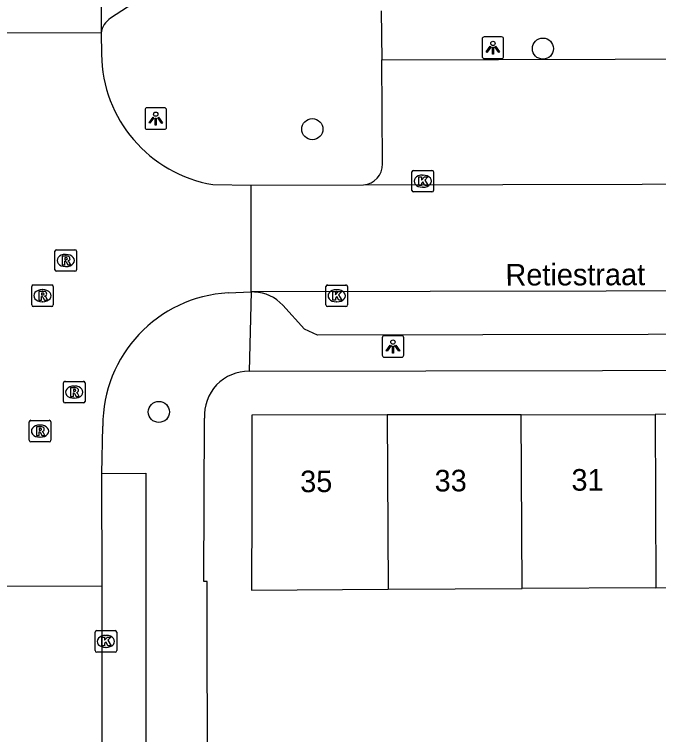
# Model space of a CAD drawing. Extents: x 160732 to 162105, y 387428 to 388479.
# Drawn here: x 161157.55 to 161187.37, y 387935.67 to 387969.02 of the extents above; entities that cross this region are included whole.
import ezdxf

# ---------------------------------------------------------------- set-up
doc = ezdxf.new("R2010")
doc.units = 0
for name, color, linetype in [('IMGEO_Boom', 7, 'Continuous'), ('IMGEO_Kolk', 7, 'Continuous'), ('IMGEO_Lichtpunt', 7, 'Continuous'), ('IMGEO_Openbare_ruimte_label', 7, 'Continuous'), ('IMGEO_Pand', 7, 'Continuous'), ('IMGEO_Pand_nummerreeks', 7, 'Continuous'), ('IMGEO_Rijbaan_lokaal_open', 7, 'Continuous'), ('IMGEO_Rioolput', 7, 'Continuous'), ('IMGEO_Voetpad_open', 7, 'Continuous')]:
    doc.layers.add(name, color=color, linetype=linetype)

msp = doc.modelspace()

# ---------------------------------------------------------------- linework, layer by layer
at = {"layer": 'IMGEO_Boom'}
for centre in [(161182.014, 387967.438), (161171.341, 387963.708), (161164.237, 387950.611)]:
    msp.add_circle(centre, 0.489, dxfattribs=at)
at = {"layer": 'IMGEO_Kolk'}
for p, q in [((161175.953, 387960.872), (161175.953, 387961.724)), ((161176.028, 387961.798), (161176.88, 387961.798)), ((161176.441, 387961.578), (161176.466, 387961.578)), ((161176.954, 387961.724), (161176.954, 387960.872)), ((161176.464, 387961.018), (161176.439, 387961.018)), ((161176.88, 387960.798), (161176.028, 387960.798)), ((161171.967, 387955.563), (161171.967, 387956.415)), ((161172.042, 387956.489), (161172.894, 387956.489)), ((161172.455, 387956.269), (161172.48, 387956.269)), ((161172.968, 387956.415), (161172.968, 387955.563)), ((161172.478, 387955.709), (161172.453, 387955.709)), ((161172.894, 387955.489), (161172.042, 387955.489)), ((161161.283, 387939.557), (161161.283, 387940.409)), ((161161.358, 387940.483), (161162.21, 387940.483)), ((161161.771, 387940.263), (161161.796, 387940.263)), ((161162.284, 387940.409), (161162.284, 387939.557)), ((161161.794, 387939.703), (161161.769, 387939.703)), ((161162.21, 387939.483), (161161.358, 387939.483))]:
    msp.add_line(p, q, dxfattribs=at)
for points in [[(161175.953, 387960.872), (161175.953, 387961.724)], [(161176.028, 387961.798), (161176.88, 387961.798)], [(161176.954, 387961.724), (161176.954, 387960.872)], [(161176.274, 387961.498), (161176.397, 387961.498), (161176.397, 387961.347), (161176.527, 387961.498), (161176.691, 387961.498), (161176.545, 387961.347), (161176.698, 387961.098), (161176.546, 387961.098), (161176.461, 387961.262), (161176.397, 387961.195), (161176.397, 387961.098), (161176.274, 387961.098), (161176.274, 387961.498)], [(161176.88, 387960.798), (161176.028, 387960.798)], [(161171.967, 387955.563), (161171.967, 387956.415)], [(161172.042, 387956.489), (161172.894, 387956.489)], [(161172.288, 387956.189), (161172.411, 387956.189), (161172.411, 387956.038), (161172.541, 387956.189), (161172.705, 387956.189), (161172.559, 387956.038), (161172.712, 387955.789), (161172.56, 387955.789), (161172.475, 387955.953), (161172.411, 387955.886), (161172.411, 387955.789), (161172.288, 387955.789), (161172.288, 387956.189)], [(161172.968, 387956.415), (161172.968, 387955.563)], [(161172.894, 387955.489), (161172.042, 387955.489)], [(161161.283, 387939.557), (161161.283, 387940.409)], [(161161.358, 387940.483), (161162.21, 387940.483)], [(161161.604, 387940.183), (161161.727, 387940.183), (161161.727, 387940.032), (161161.857, 387940.183), (161162.021, 387940.183), (161161.875, 387940.032), (161162.028, 387939.783), (161161.876, 387939.783), (161161.791, 387939.947), (161161.727, 387939.88), (161161.727, 387939.783), (161161.604, 387939.783), (161161.604, 387940.183)], [(161162.284, 387940.409), (161162.284, 387939.557)], [(161162.21, 387939.483), (161161.358, 387939.483)]]:
    msp.add_lwpolyline(points, dxfattribs=at)
for centre, start, end in [((161176.03, 387961.722), 91.552, 178.448), ((161176.03, 387961.722), 91.552, 178.448), ((161176.878, 387961.722), 1.552, 88.448), ((161176.878, 387961.722), 1.552, 88.448), ((161176.03, 387960.874), 181.552, 268.448), ((161176.03, 387960.874), 181.552, 268.448), ((161176.878, 387960.874), 271.552, 358.448), ((161176.878, 387960.874), 271.552, 358.448), ((161172.044, 387956.413), 91.552, 178.448), ((161172.044, 387956.413), 91.552, 178.448), ((161172.892, 387956.413), 1.552, 88.448), ((161172.892, 387956.413), 1.552, 88.448), ((161172.044, 387955.565), 181.552, 268.448), ((161172.044, 387955.565), 181.552, 268.448), ((161172.892, 387955.565), 271.552, 358.448), ((161172.892, 387955.565), 271.552, 358.448), ((161161.36, 387940.407), 91.552, 178.448), ((161161.36, 387940.407), 91.552, 178.448), ((161162.208, 387940.407), 1.552, 88.448), ((161162.208, 387940.407), 1.552, 88.448), ((161161.36, 387939.559), 181.552, 268.448), ((161161.36, 387939.559), 181.552, 268.448), ((161162.208, 387939.559), 271.552, 358.448), ((161162.208, 387939.559), 271.552, 358.448)]:
    msp.add_arc(centre, 0.0765, start, end, dxfattribs=at)
for centre, major_axis, ratio, start_param, end_param in [((161176.44, 387961.298), (-0.387, 0.002), 0.722429, 4.712389, 7.853982), ((161176.465, 387961.298), (-0.39, 0.002), 0.717154, 1.570796, 4.712389), ((161172.454, 387955.989), (-0.387, 0.002), 0.722429, 4.712389, 7.853982), ((161172.479, 387955.989), (-0.39, 0.002), 0.717154, 1.570796, 4.712389), ((161161.77, 387939.983), (-0.387, 0.002), 0.722429, 4.712389, 7.853982), ((161161.795, 387939.983), (-0.39, 0.002), 0.717154, 1.570796, 4.712389)]:
    msp.add_ellipse(centre, major_axis=major_axis, ratio=ratio, start_param=start_param, end_param=end_param, dxfattribs=at)
at = {"layer": 'IMGEO_Lichtpunt'}
for p, q in [((161179.201, 387967.881), (161179.201, 387967.074)), ((161179.201, 387967.881), (161179.201, 387967.074)), ((161180.103, 387967.976), (161179.295, 387967.976)), ((161180.103, 387967.976), (161179.295, 387967.976)), ((161180.197, 387967.074), (161180.197, 387967.881)), ((161180.197, 387967.074), (161180.197, 387967.881)), ((161179.295, 387966.98), (161180.103, 387966.98)), ((161179.295, 387966.98), (161180.103, 387966.98)), ((161163.596, 387964.603), (161163.596, 387963.796)), ((161163.596, 387964.603), (161163.596, 387963.796)), ((161164.498, 387964.698), (161163.69, 387964.698)), ((161164.498, 387964.698), (161163.69, 387964.698)), ((161164.592, 387963.796), (161164.592, 387964.603)), ((161164.592, 387963.796), (161164.592, 387964.603)), ((161163.69, 387963.702), (161164.498, 387963.702)), ((161163.69, 387963.702), (161164.498, 387963.702)), ((161174.575, 387954.045), (161174.575, 387953.238)), ((161174.575, 387954.045), (161174.575, 387953.238)), ((161175.477, 387954.14), (161174.669, 387954.14)), ((161175.477, 387954.14), (161174.669, 387954.14)), ((161175.571, 387953.238), (161175.571, 387954.045)), ((161175.571, 387953.238), (161175.571, 387954.045)), ((161174.669, 387953.144), (161175.477, 387953.144)), ((161174.669, 387953.144), (161175.477, 387953.144))]:
    msp.add_line(p, q, dxfattribs=at)
for points in [[(161179.575, 387967.545), (161179.614, 387967.517), (161179.426, 387967.255), (161179.388, 387967.282), (161179.575, 387967.545)], [(161179.787, 387967.517), (161179.825, 387967.544), (161180.012, 387967.282), (161179.973, 387967.254), (161179.787, 387967.517)], [(161179.677, 387967.497), (161179.724, 387967.497), (161179.724, 387967.175), (161179.677, 387967.175), (161179.677, 387967.497)], [(161163.97, 387964.267), (161164.009, 387964.239), (161163.821, 387963.977), (161163.783, 387964.004), (161163.97, 387964.267)], [(161164.072, 387964.219), (161164.119, 387964.219), (161164.119, 387963.897), (161164.072, 387963.897), (161164.072, 387964.219)], [(161164.182, 387964.239), (161164.22, 387964.266), (161164.407, 387964.004), (161164.368, 387963.976), (161164.182, 387964.239)], [(161174.949, 387953.709), (161174.988, 387953.681), (161174.8, 387953.419), (161174.762, 387953.446), (161174.949, 387953.709)], [(161175.051, 387953.661), (161175.098, 387953.661), (161175.098, 387953.339), (161175.051, 387953.339), (161175.051, 387953.661)], [(161175.161, 387953.681), (161175.199, 387953.708), (161175.386, 387953.446), (161175.347, 387953.418), (161175.161, 387953.681)]]:
    msp.add_lwpolyline(points, dxfattribs=at)
for centre in [(161179.7, 387967.679), (161164.095, 387964.401), (161175.074, 387953.843)]:
    msp.add_circle(centre, 0.0994, dxfattribs=at)
for centre, start, end in [((161179.295, 387967.881), 90, 180), ((161179.295, 387967.881), 90, 180), ((161180.103, 387967.881), 0, 90), ((161180.103, 387967.881), 0, 90), ((161179.295, 387967.074), 180, 270), ((161179.295, 387967.074), 180, 270), ((161180.103, 387967.074), 270, 0), ((161180.103, 387967.074), 270, 360), ((161163.69, 387964.603), 90, 180), ((161163.69, 387964.603), 90, 180), ((161164.498, 387964.603), 0, 90), ((161164.498, 387964.603), 0, 90), ((161163.69, 387963.796), 180, 270), ((161163.69, 387963.796), 180, 270), ((161164.498, 387963.796), 270, 0), ((161164.498, 387963.796), 270, 360), ((161174.669, 387954.045), 90, 180), ((161174.669, 387954.045), 90, 180), ((161175.477, 387954.045), 0, 90), ((161175.477, 387954.045), 0, 90), ((161174.669, 387953.238), 180, 270), ((161174.669, 387953.238), 180, 270), ((161175.477, 387953.238), 270, 0), ((161175.477, 387953.238), 270, 360)]:
    msp.add_arc(centre, 0.0946, start, end, dxfattribs=at)
at = {"layer": 'IMGEO_Pand'}
for points in [[(161174.808, 387950.47), (161168.535, 387950.459), (161168.535, 387946.227), (161168.521, 387942.361), (161174.849, 387942.396)], [(161181.005, 387950.481), (161174.808, 387950.47)], [(161174.808, 387950.47), (161174.849, 387942.396)], [(161181.005, 387950.481), (161187.204, 387950.491)], [(161181.048, 387942.431), (161181.005, 387950.481)], [(161193.403, 387950.502), (161187.204, 387950.491)], [(161187.204, 387950.491), (161187.247, 387942.466)], [(161187.247, 387942.466), (161193.447, 387942.501)], [(161174.849, 387942.396), (161181.048, 387942.431)], [(161187.247, 387942.466), (161181.048, 387942.431)]]:
    msp.add_lwpolyline(points, dxfattribs=at)
at = {"layer": 'IMGEO_Rijbaan_lokaal_open'}
for points in [[(161161.475, 388044.985), (161161.565, 387968.157)], [(161161.565, 387968.157), (161156.629, 387968.165)], [(161161.565, 387968.157), (161161.581, 387967.173)], [(161173.705, 387961.122), (161212.393, 387961.222), (161212.367, 387967.026)], [(161166.739, 387961.141), (161168.507, 387961.118)], [(161168.507, 387961.118), (161173.705, 387961.122)], [(161168.516, 387956.165), (161168.507, 387961.118)], [(161217.48, 387956.261), (161168.663, 387956.165)], [(161167.441, 387956.125), (161168.516, 387956.165)], [(161168.663, 387956.165), (161168.516, 387956.165)], [(161161.599, 387947.756), (161161.64, 387949.955)], [(161161.618, 387942.56), (161161.599, 387947.756)], [(161156.704, 387942.547), (161161.618, 387942.56)], [(161161.627, 387913.997), (161161.618, 387942.56)]]:
    msp.add_lwpolyline(points, dxfattribs=at)
for centre, radius, start, end in [((161167.769, 387967.243), 6.189, 180.6508, 260.4171), ((161167.792, 387949.983), 6.152, 93.2734, 180.2577)]:
    msp.add_arc(centre, radius, start, end, dxfattribs=at)
at = {"layer": 'IMGEO_Rioolput'}
for p, q in [((161159.427, 387957.198), (161159.427, 387958.05)), ((161159.502, 387958.124), (161160.354, 387958.124)), ((161159.915, 387957.904), (161159.94, 387957.904)), ((161160.428, 387958.05), (161160.428, 387957.198)), ((161159.938, 387957.344), (161159.913, 387957.344)), ((161160.354, 387957.124), (161159.502, 387957.124)), ((161158.349, 387955.568), (161158.349, 387956.42)), ((161158.424, 387956.494), (161159.276, 387956.494)), ((161158.837, 387956.274), (161158.862, 387956.274)), ((161159.35, 387956.42), (161159.35, 387955.568)), ((161158.86, 387955.714), (161158.835, 387955.714)), ((161159.276, 387955.494), (161158.424, 387955.494)), ((161159.817, 387951.101), (161159.817, 387951.953)), ((161159.892, 387952.027), (161160.744, 387952.027)), ((161160.818, 387951.953), (161160.818, 387951.101)), ((161160.305, 387951.807), (161160.33, 387951.807)), ((161160.328, 387951.247), (161160.303, 387951.247)), ((161160.744, 387951.027), (161159.892, 387951.027)), ((161158.31, 387950.221), (161159.162, 387950.221)), ((161158.235, 387949.295), (161158.235, 387950.147)), ((161158.723, 387950.001), (161158.748, 387950.001)), ((161159.236, 387950.147), (161159.236, 387949.295)), ((161159.162, 387949.221), (161158.31, 387949.221)), ((161158.746, 387949.441), (161158.721, 387949.441))]:
    msp.add_line(p, q, dxfattribs=at)
for points in [[(161159.427, 387957.198), (161159.427, 387958.05)], [(161159.502, 387958.124), (161160.354, 387958.124)], [(161160.428, 387958.05), (161160.428, 387957.198)], [(161160.016, 387957.822), (161159.764, 387957.824), (161159.764, 387957.424)], [(161159.764, 387957.424), (161159.888, 387957.424), (161159.888, 387957.586), (161159.899, 387957.586)], [(161159.942, 387957.743), (161159.888, 387957.743), (161159.888, 387957.662)], [(161159.888, 387957.662), (161159.94, 387957.662)], [(161159.946, 387957.557), (161160.017, 387957.424), (161160.157, 387957.424), (161160.092, 387957.55)], [(161160.354, 387957.124), (161159.502, 387957.124)], [(161158.349, 387955.568), (161158.349, 387956.42)], [(161158.424, 387956.494), (161159.276, 387956.494)], [(161158.938, 387956.192), (161158.686, 387956.194), (161158.686, 387955.794)], [(161159.35, 387956.42), (161159.35, 387955.568)], [(161158.686, 387955.794), (161158.81, 387955.794), (161158.81, 387955.956), (161158.821, 387955.956)], [(161158.864, 387956.113), (161158.81, 387956.113), (161158.81, 387956.032)], [(161158.81, 387956.032), (161158.862, 387956.032)], [(161158.868, 387955.927), (161158.939, 387955.794), (161159.079, 387955.794), (161159.014, 387955.92)], [(161159.276, 387955.494), (161158.424, 387955.494)], [(161159.817, 387951.101), (161159.817, 387951.953)], [(161159.892, 387952.027), (161160.744, 387952.027)], [(161160.818, 387951.953), (161160.818, 387951.101)], [(161160.406, 387951.725), (161160.154, 387951.727), (161160.154, 387951.327)], [(161160.332, 387951.646), (161160.278, 387951.646), (161160.278, 387951.565)], [(161160.278, 387951.565), (161160.33, 387951.565)], [(161160.154, 387951.327), (161160.278, 387951.327), (161160.278, 387951.489), (161160.289, 387951.489)], [(161160.336, 387951.46), (161160.407, 387951.327), (161160.547, 387951.327), (161160.482, 387951.453)], [(161160.744, 387951.027), (161159.892, 387951.027)], [(161158.31, 387950.221), (161159.162, 387950.221)], [(161158.235, 387949.295), (161158.235, 387950.147)], [(161158.824, 387949.919), (161158.572, 387949.921), (161158.572, 387949.521)], [(161158.75, 387949.84), (161158.696, 387949.84), (161158.696, 387949.759)], [(161159.236, 387950.147), (161159.236, 387949.295)], [(161158.572, 387949.521), (161158.696, 387949.521), (161158.696, 387949.683), (161158.707, 387949.683)], [(161158.696, 387949.759), (161158.748, 387949.759)], [(161158.754, 387949.654), (161158.825, 387949.521), (161158.965, 387949.521), (161158.9, 387949.647)], [(161159.162, 387949.221), (161158.31, 387949.221)]]:
    msp.add_lwpolyline(points, dxfattribs=at)
for centre, radius, start, end in [((161159.504, 387958.048), 0.0765, 91.552, 178.448), ((161159.504, 387958.048), 0.0765, 91.552, 178.448), ((161160.352, 387958.048), 0.0765, 1.552, 88.448), ((161160.352, 387958.048), 0.0765, 1.552, 88.448), ((161159.898, 387957.533), 0.0533, 26.0293, 88.6989), ((161159.924, 387957.851), 0.19, 274.7715, 282.9687), ((161159.948, 387957.647), 0.0964, 77.0061, 93.1865), ((161159.962, 387957.704), 0.0378, 276.6634, 79.6772), ((161160.015, 387957.712), 0.109, 350.3612, 89.416), ((161160.013, 387957.712), 0.112, 277.5842, 350.9817), ((161159.997, 387957.497), 0.108, 29.5134, 73.7905), ((161159.504, 387957.2), 0.0765, 181.552, 268.448), ((161159.504, 387957.2), 0.0765, 181.552, 268.448), ((161160.352, 387957.2), 0.0765, 271.552, 358.448), ((161160.352, 387957.2), 0.0765, 271.552, 358.448), ((161158.426, 387956.418), 0.0765, 91.552, 178.448), ((161158.426, 387956.418), 0.0765, 91.552, 178.448), ((161158.937, 387956.082), 0.109, 350.3612, 89.416), ((161159.274, 387956.418), 0.0765, 1.552, 88.448), ((161159.274, 387956.418), 0.0765, 1.552, 88.448), ((161158.82, 387955.903), 0.0533, 26.0293, 88.6989), ((161158.846, 387956.221), 0.19, 274.7715, 282.9687), ((161158.87, 387956.017), 0.0964, 77.0061, 93.1865), ((161158.884, 387956.074), 0.0378, 276.6634, 79.6772), ((161158.935, 387956.082), 0.112, 277.5842, 350.9817), ((161158.919, 387955.867), 0.108, 29.5134, 73.7905), ((161158.426, 387955.57), 0.0765, 181.552, 268.448), ((161158.426, 387955.57), 0.0765, 181.552, 268.448), ((161159.274, 387955.57), 0.0765, 271.552, 358.448), ((161159.274, 387955.57), 0.0765, 271.552, 358.448), ((161159.894, 387951.951), 0.0765, 91.552, 178.448), ((161159.894, 387951.951), 0.0765, 91.552, 178.448), ((161160.742, 387951.951), 0.0765, 1.552, 88.448), ((161160.742, 387951.951), 0.0765, 1.552, 88.448), ((161160.314, 387951.754), 0.19, 274.7715, 282.9687), ((161160.338, 387951.55), 0.0964, 77.0061, 93.1865), ((161160.352, 387951.607), 0.0378, 276.6634, 79.6772), ((161160.405, 387951.615), 0.109, 350.3612, 89.416), ((161160.403, 387951.615), 0.112, 277.5842, 350.9817), ((161160.288, 387951.436), 0.0533, 26.0293, 88.6989), ((161160.387, 387951.4), 0.108, 29.5134, 73.7905), ((161159.894, 387951.103), 0.0765, 181.552, 268.448), ((161159.894, 387951.103), 0.0765, 181.552, 268.448), ((161160.742, 387951.103), 0.0765, 271.552, 358.448), ((161160.742, 387951.103), 0.0765, 271.552, 358.448), ((161158.312, 387950.145), 0.0765, 91.552, 178.448), ((161158.312, 387950.145), 0.0765, 91.552, 178.448), ((161159.16, 387950.145), 0.0765, 1.552, 88.448), ((161159.16, 387950.145), 0.0765, 1.552, 88.448), ((161158.756, 387949.744), 0.0964, 77.0061, 93.1865), ((161158.77, 387949.801), 0.0378, 276.6634, 79.6772), ((161158.823, 387949.809), 0.109, 350.3612, 89.416), ((161158.706, 387949.63), 0.0533, 26.0293, 88.6989), ((161158.732, 387949.948), 0.19, 274.7715, 282.9687), ((161158.821, 387949.809), 0.112, 277.5842, 350.9817), ((161158.805, 387949.594), 0.108, 29.5134, 73.7905), ((161158.312, 387949.297), 0.0765, 181.552, 268.448), ((161158.312, 387949.297), 0.0765, 181.552, 268.448), ((161159.16, 387949.297), 0.0765, 271.552, 358.448), ((161159.16, 387949.297), 0.0765, 271.552, 358.448)]:
    msp.add_arc(centre, radius, start, end, dxfattribs=at)
for centre, major_axis, ratio, start_param, end_param in [((161159.914, 387957.624), (-0.387, 0.002), 0.722429, 4.712389, 7.853982), ((161159.939, 387957.624), (-0.39, 0.002), 0.717154, 1.570796, 4.712389), ((161158.836, 387955.994), (-0.387, 0.002), 0.722429, 4.712389, 7.853982), ((161158.861, 387955.994), (-0.39, 0.002), 0.717154, 1.570796, 4.712389), ((161160.304, 387951.527), (-0.387, 0.002), 0.722429, 4.712389, 7.853982), ((161160.329, 387951.527), (-0.39, 0.002), 0.717154, 1.570796, 4.712389), ((161158.722, 387949.721), (-0.387, 0.002), 0.722429, 4.712389, 7.853982), ((161158.747, 387949.721), (-0.39, 0.002), 0.717154, 1.570796, 4.712389)]:
    msp.add_ellipse(centre, major_axis=major_axis, ratio=ratio, start_param=start_param, end_param=end_param, dxfattribs=at)
at = {"layer": 'IMGEO_Voetpad_open'}
for points in [[(161163.479, 388022.652), (161163.652, 387970.452), (161163.55, 387970.033), (161163.307, 387969.717), (161162.002, 387968.854)], [(161174.53, 387969.19), (161174.563, 387966.923)], [(161174.563, 387966.923), (161212.367, 387967.026)], [(161174.593, 387962.095), (161174.563, 387966.923)], [(161168.516, 387956.165), (161168.418, 387952.495)], [(161217.496, 387954.255), (161171.575, 387954.168), (161170.974, 387954.445), (161169.968, 387955.554)], [(161168.418, 387952.495), (161217.507, 387952.589)], [(161166.481, 387932.401), (161166.474, 387942.759), (161166.323, 387942.76), (161166.352, 387950.318)], [(161161.599, 387947.756), (161163.631, 387947.771), (161163.64, 387917.113)]]:
    msp.add_lwpolyline(points, dxfattribs=at)
for centre, radius, start, end in [((161162.599, 387967.994), 1.047, 124.7717, 171.0552), ((161173.625, 387962.086), 0.968, 274.7263, 0.5039), ((161168.595, 387954.321), 1.845, 41.9236, 87.8985), ((161168.389, 387950.454), 2.041, 89.1787, 183.8184)]:
    msp.add_arc(centre, radius, start, end, dxfattribs=at)

# ---------------------------------------------------------------- texts
at = {"layer": 'IMGEO_Openbare_ruimte_label'}
msp.add_text('Retiestraat', height=1, rotation=0.1719, dxfattribs=at).set_placement((161180.282, 387956.462))
at = {"layer": 'IMGEO_Pand_nummerreeks'}
for s, p in [('35', (161170.781, 387946.89)), ('33', (161177.004, 387946.925)), ('31', (161183.339, 387946.961))]:
    msp.add_text(s, height=1, rotation=0.3207, dxfattribs=at).set_placement(p)

doc.saveas('drawing.dxf')
